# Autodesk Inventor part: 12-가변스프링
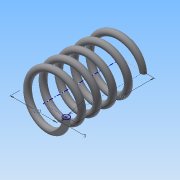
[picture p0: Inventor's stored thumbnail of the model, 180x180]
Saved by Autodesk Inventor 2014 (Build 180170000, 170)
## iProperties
Created: 2015-09
Part Number: 12-가변스프링
Material: 강철, 탄소
Document SubType Name: Modeling
Designer: study
Density: 1 g/cm^3
Appearance: 반연마
Author: study
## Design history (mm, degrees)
sketch "스케치1"
  geometry: L1 (0, 0)-(11, 0); L2 (11, 0)-(11, 36.261); L3 (11, 36.261)-(0, 36.261); L4 (0, 36.261)-(0, 0); C1 r 1.5 at (11, 0)
  constraints: 8 end point, 2 parallel, 1 centre point, 1 coincident, 1 horizontal, 1 perpendicular
  dimensions: "d0" = 3 diameter of C1; "d1" = 22 diameter of L1.end L4; "d2" = 36.2612 distance of L1.end L2.end (derived)
feature "코일1" sketch "스케치1" pitch "d3" = 10; turns "d5" = 5; dims "d4" = 36.2612 (= d2), "d6" = 0, angle "d7" = 90 deg, angle "d8" = 90 deg, "d9" = 0, "d10" = 0
node "작업 평면1"
sketch "스케치2"
  geometry: L1 (-12.5, 0)-(-9.5, 0) reference; 1 further point
  constraints: 1 horizontal alignment
extrude "돌출1" cut sketch "스케치2" stored distance "d12" = 10; taper "d13" = 0 deg
node "작업 평면2"
sketch "스케치3"
  geometry: L1 (-9.5, 0)-(-12.5, 0) reference; 1 further point
  constraints: 1 horizontal alignment
extrude "돌출2" cut sketch "스케치3" stored distance "d15" = 10; taper "d16" = 0 deg
node "솔리드1"
node "절단 모서리 투영1"
node "절단 모서리 투영2"
other parameters: "d11" = 0, "d14" = 36.2612 (= d2)
